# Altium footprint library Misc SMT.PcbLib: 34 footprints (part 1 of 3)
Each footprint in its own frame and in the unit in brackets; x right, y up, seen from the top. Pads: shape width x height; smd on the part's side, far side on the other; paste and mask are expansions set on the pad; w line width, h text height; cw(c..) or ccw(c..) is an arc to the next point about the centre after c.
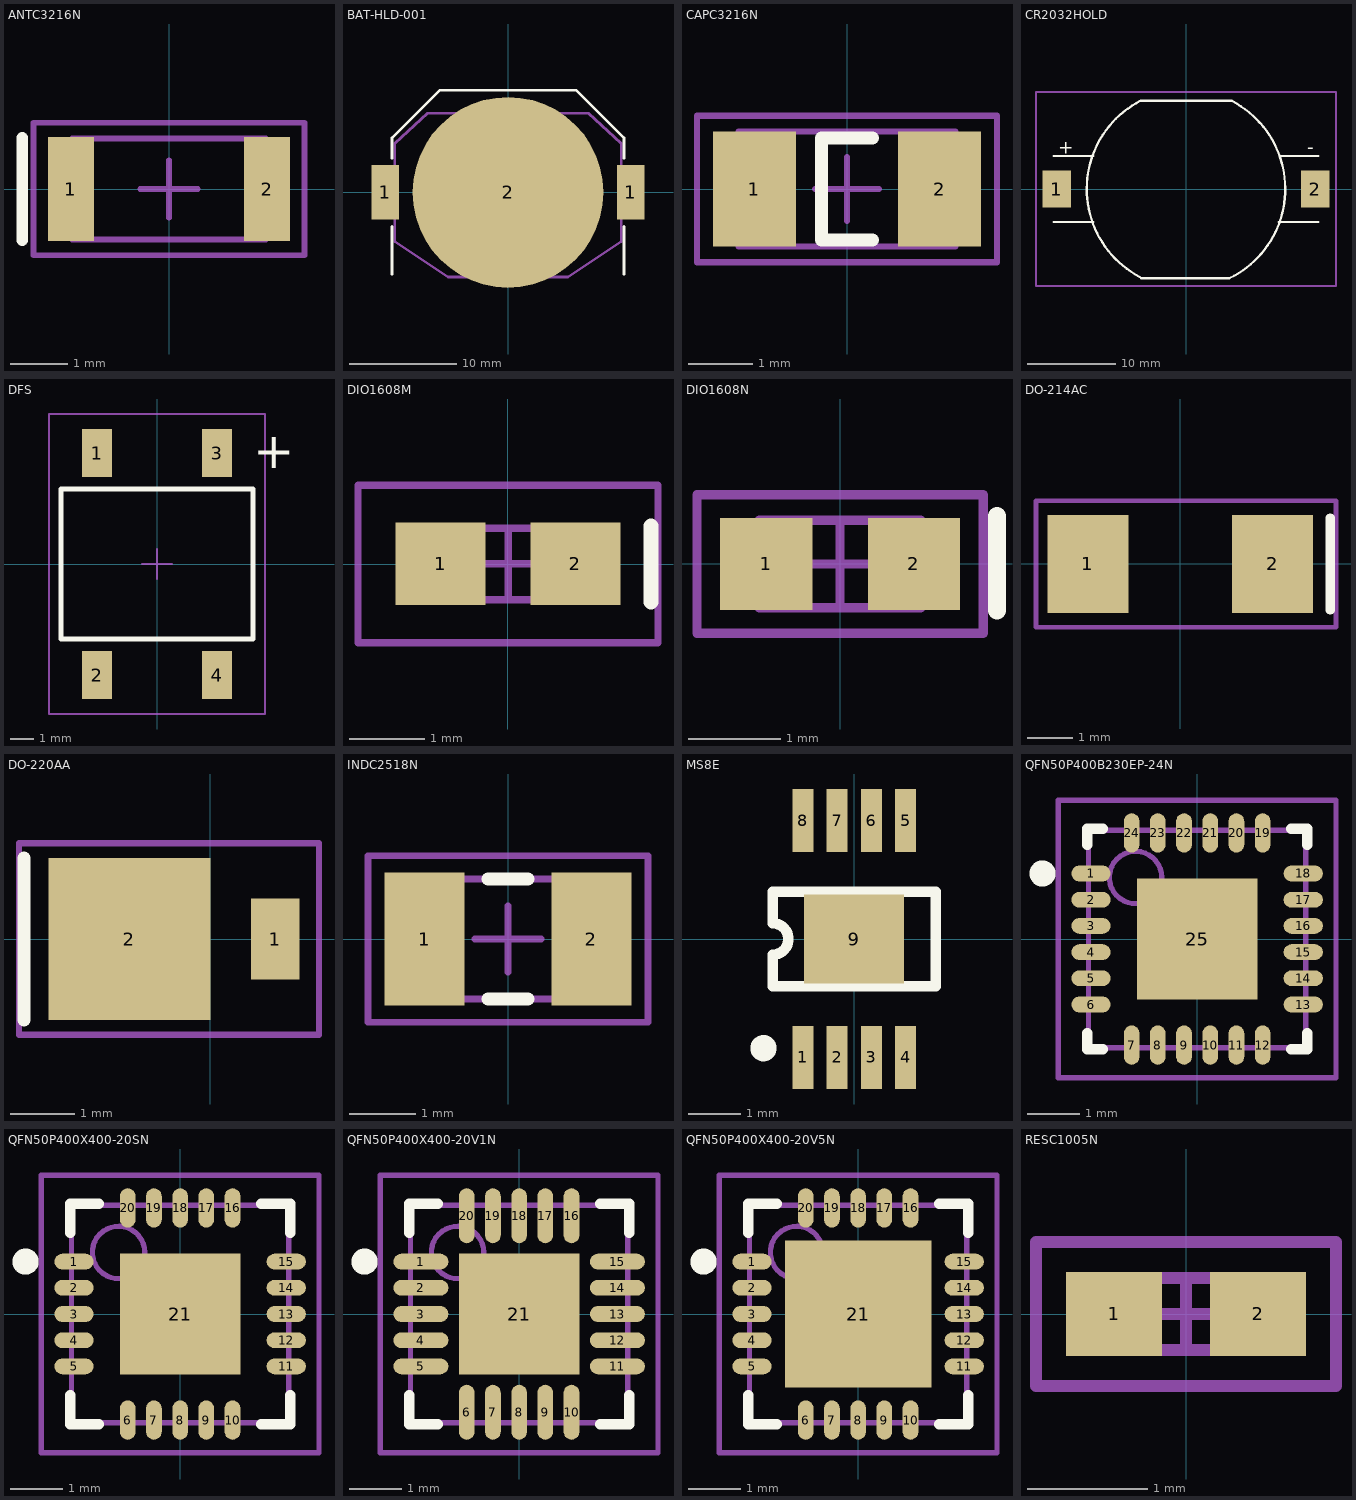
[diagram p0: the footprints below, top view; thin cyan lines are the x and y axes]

## ANTC3216N [mm] "Chip Antenna, Body 3.2x1.6mm, IPC Medium Density"
height 0.71
pads (2):
  rect 0.8x1.8 smd: 1(-1.7,0) 2(1.7,0)
Top Overlay:
  lines w0.2: -2.54,-0.889 -2.54,0.889
Mechanical 13:
  lines w0.1: -1.675,-0.875 -1.675,0.875 1.675,0.875 1.675,-0.875 -1.675,-0.875
Mechanical 15:
  lines w0.1: -0.5,0 0.5,0 ; 0,-0.5 0,0.5 ; -2.35,-1.15 -2.35,1.15 2.35,1.15 2.35,-1.15 -2.35,-1.15
3D body: height 0.71, standoff 0, extent -1.675,-0.875 1.675,0.875

## BAT-HLD-001 [mm] "CR2032 Battery Holder"
height 4.318
pads (3):
  rect 2.54x5.08 smd: 1(-11.43,0) 1(11.43,0)
  round 17.78 smd: 2(0,0)
Top Overlay:
  lines w0.254: -10.795,-7.62 -10.795,-3.175 ; -10.795,3.175 -10.795,5.08 -6.35,9.525 6.35,9.525 10.795,5.08 10.795,3.175 ; 10.795,-7.62 10.795,-3.175
Mechanical 13:
  lines w0.254: -10.541,-4.572 -10.541,4.572 -7.493,7.366 7.493,7.366 10.541,4.572 10.541,-4.572 5.588,-7.874 -5.588,-7.874 -10.541,-4.572
3D body: height 4.32, standoff 0, extent -10.541,-7.874 10.541,7.366

## CAPC3216N [mm] "Chip Capacitor, Body 3.2x1.6mm, IPC Medium Density"
height 1.35
pads (2):
  rect 1.3x1.8 smd: 1(-1.45,0) 2(1.45,0)
Top Overlay:
  lines w0.2: 0.4,-0.8 -0.4,-0.8 -0.4,0.8 0.4,0.8
Mechanical 13:
  lines w0.1: -1.7,-0.9 1.7,-0.9 1.7,0.9 -1.7,0.9 -1.7,-0.9
Mechanical 15:
  lines w0.1: -0.5,0 0.5,0 ; 0,-0.5 0,0.5 ; -2.35,-1.15 2.35,-1.15 2.35,1.15 -2.35,1.15 -2.35,-1.15
3D body: height 1.35, standoff 0, extent -1.7,-0.9 1.7,0.9

## CR2032HOLD [mm] "BU2032SM-HD-G"
height 5.3
pads (2):
  rect 3.2x4.2 smd: 1(-14.65,0) 2(14.65,0)
Top Overlay:
  lines w0.254: -15,-3.75 -10.5,-3.75 ; -15,3.75 -10.5,3.75 ; -5.229,-9.961 cw(c0,0) -5.134,10.01 5.18,10.01 ; -5.079,-10.111 4.932,-10.111 ccw(c0,0) 5.229,9.961 ; 10.5,-3.75 15,-3.75 ; 10.75,3.75 15,3.75
  text "-" at 13.75,4 h1.52
  text "+" at -14.5,4 h1.52
Mechanical 15:
  lines w0.254: -17,-11 17,-11 17,11 -17,11 -17,-11
3D body: height 5.3, standoff 0, extent -9.921,-10.23 10,9.73

## DFS [mil] "Bridge rectifier - Comchip DFxxxS"
height 100
pads (4):
  rect 50x80 smd: 1(-100,185) 2(-100,-185) 3(100,185) 4(100,-185)
Top Overlay:
  lines w7.87: -160,-125 160,-125 160,125 -160,125 -160,-125
  text "+" at 160,160 h60
Mechanical 15:
  lines w3.94: -25,0 25,0 ; 0,-25 0,25 ; -180,-250 -180,250 180,250 180,-250 -180,-250
3D body: height 100, standoff 0, extent -160,-125 160,125

## DIO1608M [mm] "Chip LED, Body 1.6x0.8mm, IPC Low Density"
height 0.85
pads (2):
  rect 1.2x1.1 smd: 1(-0.9,0) 2(0.9,0)
Top Overlay:
  lines w0.2: 1.905,-0.508 1.905,0.508
Mechanical 13:
  lines w0.1: -0.875,-0.475 0.875,-0.475 0.875,0.475 -0.875,0.475 -0.875,-0.475
Mechanical 15:
  lines w0.1: -0.475,0 0.475,0 ; 0,-0.475 0,0.475 ; -2,-1.05 2,-1.05 2,1.05 -2,1.05 -2,-1.05
3D body: height 0.85, standoff 0, extent -0.875,-0.475 0.875,0.475

## DIO1608N [mm] "Chip LED, Body 1.6x0.8mm, IPC Medium Density"
height 0.85
pads (2):
  rect 1x1 smd: 1(-0.8,0) 2(0.8,0)
Top Overlay:
  lines w0.2: 1.7,-0.5 1.7,0.516
Mechanical 13:
  lines w0.1: -0.875,-0.475 0.875,-0.475 0.875,0.475 -0.875,0.475 -0.875,-0.475
Mechanical 15:
  lines w0.1: -0.475,0 0.475,0 ; 0,-0.475 0,0.475 ; -1.55,-0.75 1.55,-0.75 1.55,0.75 -1.55,0.75 -1.55,-0.75
3D body: height 0.85, standoff 0, extent -0.875,-0.475 0.875,0.475

## DO-214AC [mil] "Surface mount diode, \"SMA\""
height 110
pads (2):
  rect 70x85 smd: 1(-80,0) 2(80,0)
Top Overlay:
  lines w7.87: 130,-40 130,40
Mechanical 15:
  lines w3.94: -125,-55 135,-55 135,55 -125,55 -125,-55

## DO-220AA [mil] "Surface mount diode, \"SMP\""
height 45
pads (2):
  rect 30x50 smd: 1(40,0)
  rect 100x100 smd: 2(-50,0)
Top Overlay:
  lines w7.87: -115,-50 -115,50
Mechanical 15:
  lines w3.94: -118.11,-59.06 -118.11,59.06 66.93,59.06 66.93,-59.06 -118.11,-59.06

## INDC2518N [mm] "Chip Inductor, Body 2.5x1.8mm, [Taiyo Yuden]"
height 1.8
pads (2):
  rect 1.2x2 smd: 1(-1.25,0) 2(1.25,0)
Top Overlay:
  lines w0.2: -0.3,-0.9 0.3,-0.9 ; -0.3,0.9 0.3,0.9
Mechanical 13:
  lines w0.1: -1.25,-0.9 -1.25,0.9 1.25,0.9 1.25,-0.9 -1.25,-0.9
Mechanical 15:
  lines w0.1: -0.5,0 0.5,0 ; 0,-0.5 0,0.5 ; -2.1,-1.25 -2.1,1.25 2.1,1.25 2.1,-1.25 -2.1,-1.25
3D body: height 1, standoff 0, extent -1.25,-0.9 1.25,0.9

## MS8E [mm] "Shrink Small Outline; 8 Leads; Body Width 3 mm; Pitch 0.65 mm"
height 1.17
pads (9):
  rect 0.4x1.2 smd: 1(-0.975,-2.25) 2(-0.325,-2.25) 3(0.325,-2.25) 4(0.975,-2.25) 5(0.975,2.25) 6(0.325,2.25) 7(-0.325,2.25) 8(-0.975,2.25)
  rect 1.9x1.7 smd: 9(0,0)
Top Overlay:
  circle w0.25: c-1.725,-2.075 r0.125
  lines w0.2: -1.55,-0.9 -1.55,-0.3 ccw(c-1.55,0) -1.55,0.3 -1.55,0.9 1.55,0.9 1.55,-0.9 -1.55,-0.9

## QFN50P400B230EP-24N [mm] "QFN, 24-Leads, Body 4x4mm, Pitch 0.5mm, IPC Medium Density"
height 1
pads (25):
  oval 0.75x0.3 smd: 1(-2.025,1.25) 2(-2.025,0.75) 3(-2.025,0.25) 4(-2.025,-0.25) 5(-2.025,-0.75) 6(-2.025,-1.25) 13(2.025,-1.25) 14(2.025,-0.75) 15(2.025,-0.25) 16(2.025,0.25) 17(2.025,0.75) 18(2.025,1.25)
  oval 0.3x0.75 smd: 7(-1.25,-2.025) 8(-0.75,-2.025) 9(-0.25,-2.025) 10(0.25,-2.025) 11(0.75,-2.025) 12(1.25,-2.025) 19(1.25,2.025) 20(0.75,2.025) 21(0.25,2.025) 22(-0.25,2.025) 23(-0.75,2.025) 24(-1.25,2.025)
  rect 2.3x2.3 smd paste-2: 25(0,0)
Top Overlay:
  circle w0.25: c-2.95,1.25 r0.125
  lines w0.2: -2.1,-1.8 -2.1,-2.1 -1.8,-2.1 ; -2.1,1.8 -2.1,2.1 -1.8,2.1 ; 1.8,-2.1 2.1,-2.1 2.1,-1.8 ; 1.8,2.1 2.1,2.1 2.1,1.8
Top Paste:
  region: -0.9,0.9 -0.9,0.2 -0.2,0.2 -0.2,0.9
  region: -0.9,-0.9 -0.2,-0.9 -0.2,-0.2 -0.9,-0.2
  region: 0.9,-0.9 0.9,-0.2 0.2,-0.2 0.2,-0.9
  region: 0.9,0.9 0.2,0.9 0.2,0.2 0.9,0.2
Mechanical 13:
  circle w0.1: c-1.175,1.175 r0.5
  lines w0.1: -2.075,-2.075 2.075,-2.075 2.075,2.075 -2.075,2.075 -2.075,-2.075
Mechanical 15:
  lines w0.1: -0.5,0 0.5,0 ; 0,-0.5 0,0.5 ; -2.65,-2.65 2.65,-2.65 2.65,2.65 -2.65,2.65 -2.65,-2.65
3D body: height 1, standoff 0, extent -2.075,-2.075 2.075,2.075

## QFN50P400X400-20SN [mm] "QFN, 20-Leads, Body 4x4mm, Pitch 0.5mm, IPC Medium Density"
height 1
pads (21):
  oval 0.75x0.3 smd: 1(-2.025,1) 2(-2.025,0.5) 3(-2.025,0) 4(-2.025,-0.5) 5(-2.025,-1) 11(2.025,-1) 12(2.025,-0.5) 13(2.025,0) 14(2.025,0.5) 15(2.025,1)
  oval 0.3x0.75 smd: 6(-1,-2.025) 7(-0.5,-2.025) 8(0,-2.025) 9(0.5,-2.025) 10(1,-2.025) 16(1,2.025) 17(0.5,2.025) 18(0,2.025) 19(-0.5,2.025) 20(-1,2.025)
  rect 2.3x2.3 smd: 21(0,0)
Top Overlay:
  circle w0.25: c-2.95,1 r0.125
  lines w0.2: -2.1,-1.55 -2.1,-2.1 -1.55,-2.1 ; -2.1,1.55 -2.1,2.1 -1.55,2.1 ; 1.55,-2.1 2.1,-2.1 2.1,-1.55 ; 1.55,2.1 2.1,2.1 2.1,1.55
Mechanical 13:
  circle w0.1: c-1.175,1.175 r0.5
  lines w0.1: -2.075,-2.075 2.075,-2.075 2.075,2.075 -2.075,2.075 -2.075,-2.075
Mechanical 15:
  lines w0.1: -0.5,0 0.5,0 ; 0,-0.5 0,0.5 ; -2.65,-2.65 2.65,-2.65 2.65,2.65 -2.65,2.65 -2.65,-2.65
3D body: height 1, standoff 0, extent -2.075,-2.075 2.075,2.075

## QFN50P400X400-20V1N [mm] "QFN, 20-Leads, Body 4x4mm, Pitch 0.5mm, IPC Medium Density"
height 1
pads (21):
  oval 1.05x0.3 smd: 1(-1.875,1) 2(-1.875,0.5) 3(-1.875,0) 4(-1.875,-0.5) 5(-1.875,-1) 11(1.875,-1) 12(1.875,-0.5) 13(1.875,0) 14(1.875,0.5) 15(1.875,1)
  oval 0.3x1.05 smd: 6(-1,-1.875) 7(-0.5,-1.875) 8(0,-1.875) 9(0.5,-1.875) 10(1,-1.875) 16(1,1.875) 17(0.5,1.875) 18(0,1.875) 19(-0.5,1.875) 20(-1,1.875)
  rect 2.3x2.3 smd: 21(0,0)
Top Overlay:
  circle w0.25: c-2.95,1 r0.125
  lines w0.2: -2.1,-1.55 -2.1,-2.1 -1.55,-2.1 ; -2.1,1.55 -2.1,2.1 -1.55,2.1 ; 1.55,-2.1 2.1,-2.1 2.1,-1.55 ; 1.55,2.1 2.1,2.1 2.1,1.55
Mechanical 13:
  circle w0.1: c-1.175,1.175 r0.5
  lines w0.1: -2.075,-2.075 -2.075,2.075 2.075,2.075 2.075,-2.075 -2.075,-2.075
Mechanical 15:
  lines w0.1: -0.5,0 0.5,0 ; 0,-0.5 0,0.5 ; -2.65,-2.65 -2.65,2.65 2.65,2.65 2.65,-2.65 -2.65,-2.65
3D body: height 1, standoff 0, extent -2.075,-2.075 2.075,2.075

## QFN50P400X400-20V5N [mm] "QFN, 20-Leads, Body 4x4mm, Pitch 0.5mm, IPC Medium Density"
height 1
pads (21):
  oval 0.75x0.3 smd: 1(-2.025,1) 2(-2.025,0.5) 3(-2.025,0) 4(-2.025,-0.5) 5(-2.025,-1) 11(2.025,-1) 12(2.025,-0.5) 13(2.025,0) 14(2.025,0.5) 15(2.025,1)
  oval 0.3x0.75 smd: 6(-1,-2.025) 7(-0.5,-2.025) 8(0,-2.025) 9(0.5,-2.025) 10(1,-2.025) 16(1,2.025) 17(0.5,2.025) 18(0,2.025) 19(-0.5,2.025) 20(-1,2.025)
  rect 2.8x2.8 smd: 21(0,0)
Top Overlay:
  circle w0.25: c-2.95,1 r0.125
  lines w0.2: -2.1,-1.55 -2.1,-2.1 -1.55,-2.1 ; -2.1,1.55 -2.1,2.1 -1.55,2.1 ; 1.55,-2.1 2.1,-2.1 2.1,-1.55 ; 1.55,2.1 2.1,2.1 2.1,1.55
Mechanical 13:
  circle w0.1: c-1.175,1.175 r0.5
  lines w0.1: -2.075,-2.075 2.075,-2.075 2.075,2.075 -2.075,2.075 -2.075,-2.075
Mechanical 15:
  lines w0.1: -0.5,0 0.5,0 ; 0,-0.5 0,0.5 ; -2.65,-2.65 2.65,-2.65 2.65,2.65 -2.65,2.65 -2.65,-2.65
3D body: height 1, standoff 0, extent -2.075,-2.075 2.075,2.075

## RESC1005N [mm] "Chip Resistor, Body 1.1x0.5mm, IPC Medium Density"
height 0.4
pads (2):
  rect 0.8x0.7 smd: 1(-0.6,0) 2(0.6,0)
Mechanical 13:
  lines w0.1: -0.55,-0.3 0.55,-0.3 0.55,0.3 -0.55,0.3 -0.55,-0.3
Mechanical 15:
  lines w0.1: -0.3,0 0.3,0 ; 0,-0.3 0,0.3 ; -1.25,-0.6 1.25,-0.6 1.25,0.6 -1.25,0.6 -1.25,-0.6
3D body: height 0.4, standoff 0, extent -0.55,-0.3 0.55,0.3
